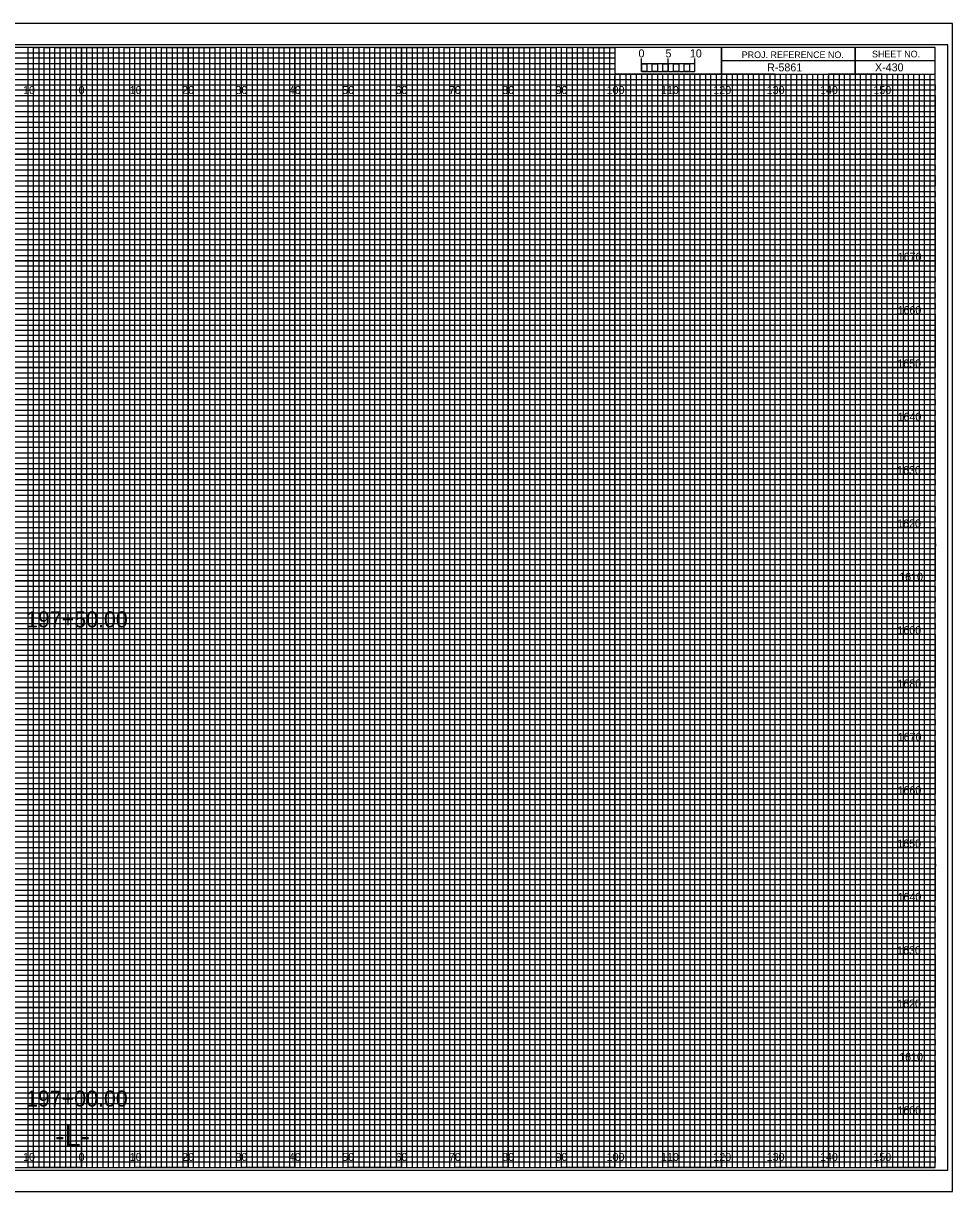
# Model space of a CAD drawing. Extents: x -13 to 323, y -5 to 6154.
# Drawn here: x 149.1 to 323.3, y 5715.5 to 5934.5 of the extents above; entities that cross this region are included whole.
import ezdxf

# ---------------------------------------------------------------- set-up
doc = ezdxf.new("R2010")
doc.units = 0
for name, color, linetype in [('Exist CMT Ground Line', 7, 'Continuous'), ('Prop Horizontal Alignment', 7, 'Continuous'), ('Prop Retaining Wall', 7, 'Continuous'), ('Prop XS Alignment Label', 7, 'Continuous'), ('Prop XS Bar Scale Labels', 7, 'Continuous'), ('Prop XS DDE', 7, 'Continuous'), ('Prop XS DDE Elevations', 7, 'Continuous'), ('Prop XS DDE Slope Text', 7, 'Continuous'), ('Prop XS Earthwork Shape', 7, 'Continuous'), ('Prop XS Elevation Labels', 7, 'Continuous'), ('Prop XS Project Number', 7, 'Continuous'), ('Prop XS Sheet Number', 7, 'Continuous'), ('Prop XS Station Labels', 7, 'Continuous'), ('Raster_Level_0', 7, 'Continuous'), ('Scratch_Level_3', 7, 'Continuous'), ('Sheet Cutting Line CELL', 7, 'Continuous')]:
    doc.layers.add(name, color=color, linetype=linetype)

msp = doc.modelspace()

# ---------------------------------------------------------------- linework, layer by layer
at = {"layer": 'Exist CMT Ground Line'}
for p, q in [((265, 5925.49), (265, 5927.9)), ((265, 5926.9), (265, 5927.9)), ((270, 5925.49), (270, 5927.9)), ((275, 5925.49), (275, 5927.9)), ((275, 5926.9), (275, 5927.9))]:
    msp.add_line(p, q, dxfattribs=at)
for points in [[(275, 5926.9), (265, 5926.9), (265, 5925.49), (275, 5925.49)], [(265, 5926.9), (266, 5926.9), (266, 5925.49), (265, 5925.49)], [(267, 5926.9), (268, 5926.9), (268, 5925.49), (267, 5925.49)], [(269, 5926.9), (270, 5926.9), (270, 5925.49), (269, 5925.49)], [(271, 5926.9), (272, 5926.9), (272, 5925.49), (271, 5925.49)], [(273, 5926.9), (274, 5926.9), (274, 5925.49), (273, 5925.49)]]:
    msp.add_lwpolyline(points, close=True, dxfattribs=at)
at = {"layer": 'Prop Retaining Wall'}
for p, q in [((0, 5929), (260, 5929)), ((260, 5929), (260, 5927.98)), ((260, 5927.98), (0, 5927.98)), ((0, 5927), (260, 5927)), ((260, 5927), (260, 5925.89)), ((260, 5925.89), (0, 5925.89)), ((0, 5924), (320, 5924))]:
    msp.add_line(p, q, dxfattribs=at)
for points in [[(0, 5923), (270, 5923), (320, 5923), (320, 5922), (0, 5922)], [(0, 5921), (320, 5921), (320, 5919), (0, 5919)], [(0, 5918), (320, 5918), (320, 5917), (0, 5916.98)], [(0, 5916), (320, 5916), (320, 5914), (0, 5914)], [(0, 5913), (320, 5913), (320, 5912), (0, 5912)], [(0, 5911), (320, 5911), (320, 5909), (0, 5909)], [(0, 5908), (320, 5908), (320, 5907), (0, 5907)], [(0, 5906), (320, 5906), (320, 5904), (0, 5904)], [(0, 5903), (320, 5903), (320, 5902), (0, 5902)], [(0, 5901), (320, 5901), (320, 5899), (0, 5899)], [(0, 5898), (320, 5898), (320, 5897), (0, 5897)], [(0, 5896), (320, 5896), (320, 5893.95), (320, 5893), (320, 5892), (0, 5892)], [(0, 5894), (320, 5894), (320, 5893), (0, 5893)], [(0, 5891), (320, 5891), (320, 5889), (0, 5889.03)], [(0, 5889.03), (320, 5889), (320, 5888), (0, 5888)], [(0, 5887), (320, 5887), (320, 5886), (0, 5886)], [(0, 5884), (320, 5884), (320, 5883), (0, 5883)], [(0, 5882), (320, 5882), (320, 5881), (0, 5881)], [(-0.07, 5878.89), (320, 5878.89), (320, 5877.88), (-0.07, 5877.88)], [(0, 5877), (320, 5877), (320, 5876), (0, 5876)], [(0, 5874), (320, 5874), (320, 5873), (0, 5873)], [(0, 5872), (320, 5872), (320, 5871), (0, 5871)], [(0, 5869), (320, 5869), (320, 5868), (0, 5868)], [(0, 5867), (320, 5867), (320, 5866), (0, 5866)], [(0, 5864), (320, 5864), (320, 5863), (0, 5863)], [(0, 5862), (320, 5862), (320, 5861), (0, 5861)], [(0, 5859), (320, 5859), (319.99, 5857.98), (0, 5858)], [(0, 5857), (320, 5857), (320, 5856), (0, 5856)], [(0, 5854), (320, 5854), (320, 5853), (0, 5853)], [(0, 5852), (320, 5852), (320, 5851), (0, 5851)], [(0, 5849), (320, 5849), (320, 5848), (0, 5848)], [(0, 5847), (320, 5847), (320, 5846), (0, 5846)], [(0, 5844), (320, 5844), (320, 5843), (0, 5843)], [(0, 5842), (320, 5842), (320, 5841), (0, 5841)], [(0, 5839), (320, 5839), (320, 5838), (0, 5838)], [(0, 5836.99), (320.07, 5836.91), (320, 5836), (0, 5836)], [(0, 5834), (320, 5834), (320, 5833), (0, 5833)], [(0, 5832), (320, 5832), (320, 5831), (0, 5831)], [(0, 5829), (320, 5829), (320, 5828), (0, 5828)], [(0, 5827), (320, 5827), (320, 5826), (0, 5826)], [(0, 5824), (320, 5824), (320, 5823), (0, 5823)], [(0, 5822), (320, 5822), (320, 5821), (0, 5821)], [(0, 5819), (320, 5819), (320, 5818), (0, 5818)], [(0, 5817), (320, 5817), (320, 5816), (0, 5816)], [(0, 5814), (320, 5814), (320, 5813), (0, 5813)], [(0, 5812), (320, 5812), (320, 5811), (0, 5811)], [(0, 5809), (320, 5809), (320, 5808), (0, 5808)], [(0, 5807), (320, 5807), (320, 5806), (0, 5806)], [(0, 5804), (320, 5804), (320, 5803), (0, 5803)], [(0, 5802), (320, 5802), (320, 5801), (0, 5801)], [(0, 5799), (320, 5799), (319.99, 5797.98), (0, 5798)], [(0, 5797), (320, 5797), (320, 5796), (0, 5796)], [(0, 5794), (320, 5794), (320, 5793), (0, 5793)], [(0, 5792), (320, 5792), (320, 5791), (0, 5791)], [(0, 5789), (320, 5789), (320, 5788), (0, 5788)], [(0, 5787), (320, 5787), (320, 5786), (0, 5786)], [(0, 5784), (320, 5784), (320, 5783), (0, 5783)], [(0, 5782), (320, 5782), (320, 5781), (0, 5781)], [(0, 5779), (320, 5779), (320, 5778), (0, 5778)], [(0, 5776.99), (320.07, 5776.91), (320, 5776), (0, 5776)], [(0, 5774), (320, 5774), (320, 5773), (0, 5773)], [(0, 5772), (320, 5772), (320, 5771), (0, 5771)], [(0, 5769), (320, 5769), (320, 5768), (0, 5768)], [(0, 5767), (320, 5767), (320, 5766), (0, 5766)], [(0, 5764), (320, 5764), (320, 5763), (0, 5763)], [(0, 5762), (320, 5762), (320, 5761), (0, 5761)], [(0, 5759), (320, 5759), (320, 5758), (0, 5758)], [(0, 5757), (320, 5757), (320, 5756), (0, 5756)], [(0, 5754), (320, 5754), (320, 5753), (0, 5753)], [(0, 5752), (320, 5752), (320, 5751), (0, 5751)], [(0, 5749), (320, 5749), (320, 5748), (0, 5748)], [(0, 5747), (320, 5747), (320, 5746), (0, 5746)], [(0, 5744), (320, 5744), (320, 5743), (0, 5743)], [(0, 5742), (320, 5742), (320, 5741), (0, 5741)], [(0, 5739), (320, 5739), (320, 5738), (0, 5738)], [(0, 5737), (320, 5737), (320, 5736), (0, 5736)], [(0, 5734), (320, 5734), (320, 5733), (0, 5733)], [(0, 5732), (320, 5732), (320, 5731), (0, 5731)], [(0, 5729), (320, 5729), (320, 5728), (0, 5728)], [(0, 5727), (320, 5727), (320, 5726), (0, 5726)], [(0, 5724), (320, 5724), (320, 5723), (0, 5723)], [(0, 5722), (320, 5722), (320, 5721), (0, 5721)]]:
    msp.add_lwpolyline(points, dxfattribs=at)
at = {"layer": 'Prop XS Alignment Label'}
for p, q in [((305, 5930), (305, 5925)), ((305, 5925), (305, 5930)), ((280, 5927.5), (280, 5925)), ((320, 5927.49), (280, 5927.49)), ((280, 5925), (320, 5925))]:
    msp.add_line(p, q, dxfattribs=at)
for points in [[(320, 5930), (0, 5930), (0, 5720), (320, 5720)], [(280, 5930), (260, 5930), (260, 5925.03), (280, 5925.03)], [(320, 5930), (280, 5930), (280, 5925), (320, 5925)]]:
    msp.add_lwpolyline(points, close=True, dxfattribs=at)
at = {"layer": 'Prop XS DDE'}
msp.add_lwpolyline([(-13.4, 5715.5), (323.3, 5715.5), (323.3, 5934.5), (-13.4, 5934.5)], close=True, dxfattribs=at)
at = {"layer": 'Prop XS DDE Elevations'}
for p, q in [((150, 5720), (150, 5930)), ((160, 5720), (160, 5930)), ((170, 5720), (170, 5930)), ((180, 5720), (180, 5930)), ((190, 5720), (190, 5930)), ((200, 5720), (200, 5930)), ((210, 5720), (210, 5930)), ((220, 5720), (220, 5930)), ((230, 5720), (230, 5930)), ((240, 5720), (240, 5930)), ((250, 5720), (250, 5930)), ((260, 5720), (260, 5924.69)), ((270, 5720), (270, 5924.69)), ((280, 5720), (280, 5924.69)), ((290, 5720), (290, 5924.69)), ((300, 5720), (300, 5924.69)), ((310, 5720), (310, 5924.69)), ((0, 5920), (320, 5920)), ((0, 5910), (320, 5910)), ((0, 5900), (320, 5900)), ((0, 5890), (320, 5890)), ((0, 5880), (320, 5880)), ((0, 5870), (320, 5870)), ((0, 5860), (320, 5860)), ((0, 5850), (320, 5850)), ((0, 5840), (320, 5840)), ((0, 5830), (320, 5830)), ((0, 5820), (320, 5820)), ((0, 5810), (320, 5810)), ((0, 5800), (320, 5800)), ((0, 5790), (320, 5790)), ((0, 5780), (320, 5780)), ((0, 5770), (320, 5770)), ((0, 5760), (320, 5760)), ((0, 5750), (320, 5750)), ((0, 5740), (320, 5740)), ((0, 5730), (320, 5730))]:
    msp.add_line(p, q, dxfattribs=at)
at = {"layer": 'Prop XS DDE Slope Text'}
msp.add_lwpolyline([(-10.8, 5719.5), (322.4, 5719.5), (322.4, 5930.5), (-10.8, 5930.5)], close=True, dxfattribs=at)
at = {"layer": 'Prop XS Earthwork Shape'}
for p, q in [((150, 5930), (140, 5930)), ((150, 5720), (150, 5930)), ((170, 5930), (160, 5930)), ((160, 5930), (160, 5720)), ((170, 5720), (170, 5930)), ((190, 5930), (180, 5930)), ((180, 5930), (180, 5720)), ((190, 5720), (190, 5930)), ((210, 5930), (200, 5930)), ((200, 5930), (200, 5720)), ((210, 5720), (210, 5930)), ((230, 5930), (220, 5930)), ((220, 5930), (220, 5720)), ((230, 5720), (230, 5930)), ((250, 5930), (240, 5930)), ((240, 5930), (240, 5720)), ((250, 5720), (250, 5930)), ((260, 5930), (260, 5720)), ((270, 5720), (270, 5925)), ((290, 5925), (280, 5925)), ((280, 5925), (280, 5720)), ((290, 5720), (290, 5925)), ((310, 5925), (300, 5925)), ((300, 5925), (300, 5720)), ((310, 5720), (310, 5925)), ((160, 5720), (150, 5720)), ((180, 5720), (170, 5720)), ((200, 5720), (190, 5720)), ((220, 5720), (210, 5720)), ((240, 5720), (230, 5720)), ((260, 5720), (250, 5720)), ((280, 5720), (270, 5720)), ((300, 5720), (290, 5720)), ((320, 5720), (310, 5720)), ((320, 5720), (320, 5720))]:
    msp.add_line(p, q, dxfattribs=at)
for points in [[(0, 5920), (320, 5920), (320, 5910), (0, 5910)], [(0, 5900), (320, 5900), (320, 5890), (0, 5890)], [(0, 5880), (320, 5880), (320, 5870), (0, 5870)], [(0, 5860), (320, 5860), (320, 5850), (0, 5850)], [(0, 5840), (320, 5840), (320, 5830), (0, 5830)], [(0, 5820), (320, 5820), (320, 5810), (0, 5810)], [(0, 5800), (320, 5800), (320, 5790), (0, 5790)], [(0, 5780), (320, 5780), (320, 5770), (0, 5770)], [(0, 5760), (320, 5760), (320, 5750), (0, 5750)], [(0, 5740), (320, 5740), (320, 5730), (0, 5730)]]:
    msp.add_lwpolyline(points, dxfattribs=at)
at = {"layer": 'Prop XS Elevation Labels'}
for p, q in [((267, 5925), (266.01, 5925)), ((266.01, 5925), (266.01, 5720)), ((267, 5720), (267, 5925)), ((269, 5925), (268, 5925)), ((268, 5925), (268, 5720)), ((269, 5720), (269, 5925)), ((266.01, 5720), (265, 5720)), ((268, 5720), (267, 5720))]:
    msp.add_line(p, q, dxfattribs=at)
for points in [[(150, 5720), (151, 5720), (151, 5930), (152, 5930), (152, 5720)], [(152, 5720), (153, 5720), (153, 5930), (154, 5930), (154, 5720)], [(155, 5720), (156, 5720), (156, 5930), (157, 5930), (157, 5720)], [(157, 5720), (158, 5720), (158, 5930), (159, 5930), (159, 5720)], [(160, 5720), (161, 5720), (161, 5930), (162, 5930), (162, 5720)], [(162, 5720), (163, 5720), (163, 5930), (164, 5930), (164, 5720)], [(165, 5720), (166, 5720), (166, 5930), (167, 5930), (167, 5720)], [(167, 5720), (168, 5720), (168, 5930), (169, 5930), (169, 5720)], [(170, 5720), (171, 5720), (171, 5930), (172, 5930), (172, 5720)], [(172, 5720), (173, 5720), (173, 5930), (174, 5930), (174, 5720)], [(175, 5720), (176, 5720), (176, 5930), (177, 5930), (177, 5720)], [(177, 5720), (178, 5720), (178, 5930), (179, 5930), (179, 5720)], [(180, 5720), (181, 5720), (181, 5930), (182, 5930), (182, 5720)], [(182, 5720), (183, 5720), (183, 5930), (184, 5930), (184, 5720)], [(185, 5720), (186, 5720), (186, 5930), (187, 5930), (187, 5720)], [(187, 5720), (188, 5720), (188, 5930), (189, 5930), (189, 5720)], [(190, 5720), (191, 5720), (191, 5930), (192, 5930), (192, 5720)], [(192, 5720), (193, 5720), (193, 5930), (194, 5930), (194, 5720)], [(195, 5720), (196, 5720), (196, 5930), (197, 5930), (197, 5720)], [(197, 5720), (198, 5720), (198, 5930), (199, 5930), (199, 5720)], [(200, 5720), (201, 5720), (201, 5930), (202, 5930), (202, 5720)], [(202, 5720), (203, 5720), (203, 5930), (204, 5930), (204, 5720)], [(205, 5720), (206, 5720), (206, 5930), (207, 5930), (207, 5720)], [(207, 5720), (208, 5720), (208, 5930), (209, 5930), (209, 5720)], [(210, 5720), (211, 5720), (211, 5930), (212, 5930), (212, 5720)], [(212, 5720), (213, 5720), (213, 5930), (214, 5930), (214, 5720)], [(215, 5720), (216, 5720), (216, 5930), (217, 5930), (217, 5720)], [(217, 5720), (218, 5720), (218, 5930), (219, 5930), (219, 5720)], [(220, 5720), (221, 5720), (221, 5930), (222, 5930), (222, 5720)], [(222, 5720), (223, 5720), (223, 5930), (224, 5930), (224, 5720)], [(225, 5720), (226, 5720), (226, 5930), (227, 5930), (227, 5720)], [(227, 5720), (228, 5720), (228, 5930), (229, 5930), (229, 5720)], [(230, 5720), (231, 5720), (231, 5930), (232, 5930), (232, 5720)], [(232, 5720), (233, 5720), (233, 5930), (234, 5930), (234, 5720)], [(235, 5720), (236, 5720), (236, 5930), (237, 5930), (237, 5720)], [(237, 5720), (238, 5720), (238, 5930), (239, 5930), (239, 5720)], [(240, 5720), (241, 5720), (241, 5930), (242, 5930), (242, 5720)], [(242, 5720), (243, 5720), (243, 5930), (244, 5930), (244, 5720)], [(245, 5720), (246, 5720), (246, 5930), (247, 5930), (247, 5720)], [(247, 5720), (248, 5720), (248, 5930), (249, 5930), (249, 5720)], [(250, 5720), (251, 5720), (251, 5930), (252, 5930), (252, 5720)], [(252, 5720), (253, 5720), (253, 5930), (254, 5930), (254, 5720)], [(255, 5720), (256, 5720), (256, 5930), (257, 5930), (257, 5720)], [(257, 5720), (258, 5720), (258, 5930), (259, 5930), (259, 5720)], [(260, 5720), (261, 5720), (261, 5925), (262.02, 5925), (262.02, 5720)], [(262, 5720), (263, 5720), (263, 5925), (263.99, 5925), (263.99, 5720)], [(270, 5720), (270.98, 5720), (270.98, 5925), (272, 5925), (272, 5720)], [(272, 5720), (273, 5720), (273, 5925), (274.05, 5925), (274.05, 5720)], [(275, 5720), (276, 5720), (276, 5925), (277, 5925), (277, 5720)], [(277, 5720), (278, 5720), (278, 5925), (279, 5925), (279, 5720)], [(280, 5720), (281, 5720), (281, 5925), (282, 5925), (282, 5720)], [(282, 5720), (283, 5720), (283, 5925), (284, 5925), (284, 5720)], [(285, 5720), (286, 5720), (286, 5925), (287, 5925), (287, 5720)], [(287, 5720), (288, 5720), (288, 5925), (289, 5925), (289, 5720)], [(290, 5720), (291, 5720), (291, 5925), (292, 5925), (292, 5720)], [(292, 5720), (293, 5720), (293, 5925), (294, 5925), (294, 5720)], [(295, 5720), (296, 5720), (296, 5925), (297, 5925), (297, 5720)], [(297, 5720), (298, 5720), (298, 5925), (299, 5925), (299, 5720)], [(300, 5720), (301, 5720), (301, 5925), (302, 5925), (302, 5720)], [(302, 5720), (303, 5720), (303, 5925), (304, 5925), (304, 5720)], [(305, 5720), (306, 5720), (306, 5925), (307, 5925), (307, 5720)], [(307, 5720), (308, 5720), (308, 5925), (309, 5925), (309, 5720)], [(310, 5720), (311, 5720), (311, 5925), (312, 5925), (312, 5720)], [(312, 5720), (313, 5720), (313, 5925), (314, 5925), (314, 5720)], [(315, 5720), (316, 5720), (316, 5925), (317, 5925), (317, 5720)], [(317, 5720), (318, 5720), (318, 5925), (319, 5925), (319, 5720)]]:
    msp.add_lwpolyline(points, dxfattribs=at)
at = {"layer": 'Prop XS Station Labels'}
for points in [[(145, 5720), (155, 5720), (155, 5930), (165, 5930), (165, 5720), (175, 5720), (175, 5930), (185, 5930), (185, 5720), (195, 5720), (195, 5930), (205, 5930), (205, 5720), (215, 5720), (215, 5930), (225, 5930), (225, 5720), (235, 5720), (235, 5930), (245, 5930), (245, 5720), (255, 5720), (255, 5930), (259.93, 5930), (260, 5930), (260, 5925), (264.99, 5925), (264.99, 5720), (275, 5720), (275, 5925), (285, 5925), (285, 5720), (295, 5720), (295, 5925), (305, 5925), (305, 5720), (315, 5720), (315, 5925)], [(0, 5925), (275, 5925)], [(0, 5905), (320, 5905), (320, 5915), (0, 5915)], [(0, 5885), (320, 5885), (320, 5895), (0, 5895)], [(0, 5865), (320, 5865), (320, 5875), (0, 5875)], [(0, 5845), (320, 5845), (320, 5855), (0, 5855)], [(0, 5825), (320, 5825), (320, 5835), (0, 5835)], [(0, 5805), (320, 5805), (320, 5815), (0, 5815)], [(0, 5785), (320, 5785), (320, 5795), (0, 5795)], [(0, 5765), (320, 5765), (320, 5775), (0, 5775)], [(0, 5745), (320, 5745), (320, 5755), (0, 5755)], [(0, 5725), (320, 5725), (320, 5735), (0, 5735)]]:
    msp.add_lwpolyline(points, dxfattribs=at)
at = {"layer": 'Sheet Cutting Line CELL'}
for p, q in [((323.3, 5934.5), (-13.4, 5934.5)), ((-13.4, 5715.5), (323.3, 5715.5))]:
    msp.add_line(p, q, dxfattribs=at)

# ---------------------------------------------------------------- texts
at = {"layer": 'Exist CMT Ground Line'}
msp.add_text('0', height=1.5, dxfattribs=at).set_placement((264.41, 5928.12))
at = {"layer": 'Prop Horizontal Alignment'}
for s, p in [('197+50.00', (149.59, 5821.28)), ('197+00.00', (149.59, 5731.45))]:
    msp.add_text(s, height=3, dxfattribs=at).set_placement(p)
at = {"layer": 'Prop XS Alignment Label'}
for s, height, p in [('PROJ. REFERENCE NO.', 1.25, (283.77, 5927.99)), ('SHEET NO.', 1.25, (308.19, 5928.12)), ('-L-', 4, (155.06, 5724))]:
    msp.add_text(s, height=height, dxfattribs=at).set_placement(p)
at = {"layer": 'Prop XS Bar Scale Labels'}
for s, p in [('5', (269.47, 5928.12)), ('10', (274.04, 5928.12))]:
    msp.add_text(s, height=1.5, dxfattribs=at).set_placement(p)
at = {"layer": 'Prop XS Project Number'}
msp.add_text('R-5861', height=1.5, dxfattribs=at).set_placement((288.53, 5925.5))
at = {"layer": 'Prop XS Sheet Number'}
msp.add_text('X-430', height=1.5, dxfattribs=at).set_placement((308.74, 5925.51))
at = {"layer": 'Raster_Level_0'}
for s, p in [('10', (149.04, 5921.25)), ('0', (159.45, 5921.25)), ('0', (159.45, 5921.25)), ('10', (169.04, 5921.25)), ('20', (178.86, 5921.25)), ('30', (188.86, 5921.25)), ('40', (198.86, 5921.25)), ('50', (208.86, 5921.25)), ('60', (218.86, 5921.25)), ('70', (228.86, 5921.25)), ('80', (238.86, 5921.25)), ('90', (248.86, 5921.25)), ('100', (258.44, 5921.25)), ('110', (268.62, 5921.25)), ('120', (278.44, 5921.25)), ('130', (288.44, 5921.25)), ('140', (298.44, 5921.25)), ('150', (308.44, 5921.25)), ('10', (149.04, 5721.25)), ('0', (159.45, 5721.25)), ('0', (159.45, 5721.25)), ('10', (169.04, 5721.25)), ('20', (178.86, 5721.25)), ('30', (188.86, 5721.25)), ('40', (198.86, 5721.25)), ('50', (208.86, 5721.25)), ('60', (218.86, 5721.25)), ('70', (228.86, 5721.25)), ('80', (238.86, 5721.25)), ('90', (248.86, 5721.25)), ('100', (258.44, 5721.25)), ('110', (268.62, 5721.25)), ('120', (278.44, 5721.25)), ('130', (288.44, 5721.25)), ('140', (298.44, 5721.25)), ('150', (308.44, 5721.25))]:
    msp.add_text(s, height=1.5, dxfattribs=at).set_placement(p)
at = {"layer": 'Scratch_Level_3'}
for s, p in [('1670', (313, 5890)), ('1660', (312.97, 5880)), ('1650', (312.92, 5870)), ('1640', (312.97, 5860)), ('1630', (312.89, 5850)), ('1620', (312.9, 5840)), ('1610', (313.28, 5830)), ('1600', (312.95, 5820)), ('1680', (312.95, 5810)), ('1670', (313, 5800)), ('1660', (312.97, 5790)), ('1650', (312.92, 5780)), ('1640', (312.97, 5770)), ('1630', (312.89, 5760)), ('1620', (312.9, 5750)), ('1610', (313.28, 5740)), ('1600', (312.95, 5730))]:
    msp.add_text(s, height=1.5, dxfattribs=at).set_placement(p)

doc.saveas('drawing.dxf')
